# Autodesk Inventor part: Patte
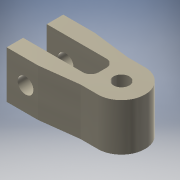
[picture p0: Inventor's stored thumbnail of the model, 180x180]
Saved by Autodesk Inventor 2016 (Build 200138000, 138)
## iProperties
Shininess: 20.0
Angle Display Precision: 2
Document Length Units: 11269
Document Angle Units: 11279
Document Time Units: 11290
Document Mass Units: 11283
Document Length Units Precision: 3
Document Angle Units Precision: 2
Created: 2002-09
Part Number: Patte
Material: Générique
Document SubType Name: Modélisation
Designer: administrateur
Mass: 42.8294 g
Surface Area: 125.095 cm^2
Volume: 42.8294 cm^3
Density: 1 g/cm^3
Appearance: Par défaut
Density: 0.0
Volumn: 0.0
Area: 0.0
PropertySet Name: Model Information
Control State: 0
Master: False
Checked Out: False
Author: administrateur
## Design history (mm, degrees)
feature "Base1"
node "Solide1"
node "Corps solides"
node "Corps surfaciques"
